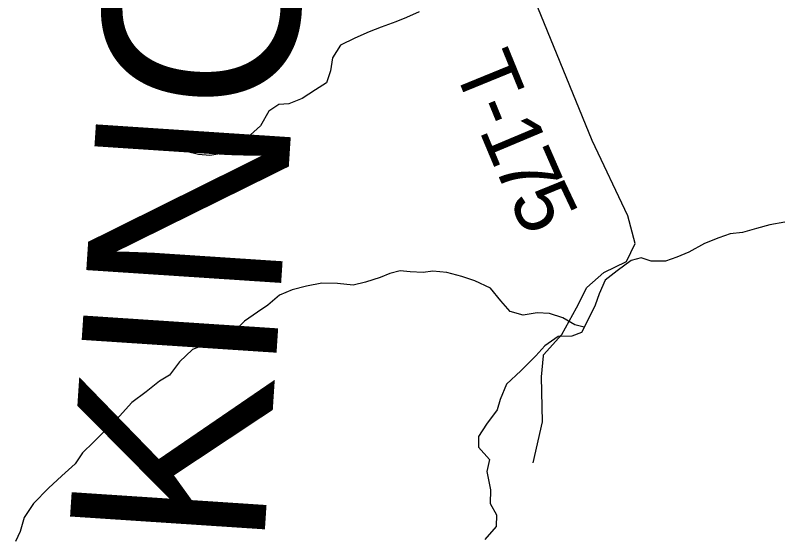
# Model space of a CAD drawing. Extents: x 0 to 42.5, y 0 to 22.
# Drawn here: x 8.1944 to 8.5674, y 14.792 to 15.0445 of the extents above; entities that cross this region are included whole.
import ezdxf

# ---------------------------------------------------------------- set-up
doc = ezdxf.new("R2010")
doc.units = 0
for name, color, linetype in [('GM_X_County_Text', 7, 'Continuous'), ('GM_X_Minor_River', 7, 'Continuous'), ('GM_X_Township_Road', 7, 'Continuous'), ('GM_X_Township_Road_Text', 7, 'Continuous')]:
    doc.layers.add(name, color=color, linetype=linetype)

msp = doc.modelspace()

# ---------------------------------------------------------------- linework, layer by layer
at = {"layer": 'GM_X_Minor_River'}
for p, q in [((8.38404, 15.04345), (8.37891, 15.0414)), ((8.39012, 15.04625), (8.38404, 15.04345)), ((8.37891, 15.0414), (8.37169, 15.03879)), ((8.366, 15.03655), (8.35897, 15.03356)), ((8.37169, 15.03879), (8.366, 15.03655)), ((8.35897, 15.03356), (8.35194, 15.03019)), ((8.35194, 15.03019), (8.34811, 15.02396)), ((8.34811, 15.02396), (8.34712, 15.01771)), ((8.34712, 15.01771), (8.34518, 15.01184)), ((8.34518, 15.01184), (8.33986, 15.00846)), ((8.33986, 15.00846), (8.33339, 15.00433)), ((8.33339, 15.00433), (8.32693, 15.00172)), ((8.32219, 15.00137), (8.31725, 14.99818)), ((8.32693, 15.00172), (8.32219, 15.00137)), ((8.31725, 14.99818), (8.31322, 14.991)), ((8.31322, 14.991), (8.30674, 14.98516)), ((8.30674, 14.98516), (8.3016, 14.98178)), ((8.25427, 14.98171), (8.24745, 14.98251)), ((8.26013, 14.98072), (8.25427, 14.98171)), ((8.26505, 14.98012), (8.26013, 14.98072)), ((8.27242, 14.97894), (8.26505, 14.98012)), ((8.3016, 14.98178), (8.29343, 14.97747)), ((8.27791, 14.97852), (8.27242, 14.97894)), ((8.2832, 14.97716), (8.27791, 14.97852)), ((8.28869, 14.97675), (8.2832, 14.97716)), ((8.29343, 14.97747), (8.28869, 14.97675)), ((8.38088, 14.92077), (8.37594, 14.91948)), ((8.3858, 14.92036), (8.38088, 14.92077)), ((8.39204, 14.91994), (8.3858, 14.92036)), ((8.39678, 14.92067), (8.39204, 14.91994)), ((8.40359, 14.92006), (8.39678, 14.92067)), ((8.3712, 14.91761), (8.36418, 14.91538)), ((8.37594, 14.91948), (8.3712, 14.91761)), ((8.41078, 14.91811), (8.40359, 14.92006)), ((8.4172, 14.91599), (8.41078, 14.91811)), ((8.33557, 14.91329), (8.32855, 14.91163)), ((8.34296, 14.91476), (8.33557, 14.91329)), ((8.35054, 14.91471), (8.34296, 14.91476)), ((8.35811, 14.9139), (8.35054, 14.91471)), ((8.36418, 14.91538), (8.35811, 14.9139)), ((8.42475, 14.91233), (8.4172, 14.91599)), ((8.32855, 14.91163), (8.32247, 14.90901)), ((8.42981, 14.90623), (8.42475, 14.91233)), ((8.32247, 14.90901), (8.31676, 14.90412)), ((8.43432, 14.90108), (8.42981, 14.90623)), ((8.31676, 14.90412), (8.31181, 14.90074)), ((8.31181, 14.90074), (8.30553, 14.89642)), ((8.44056, 14.89934), (8.43432, 14.90108)), ((8.44738, 14.90043), (8.44056, 14.89934)), ((8.45344, 14.9002), (8.44738, 14.90043)), ((8.45986, 14.89807), (8.45344, 14.9002)), ((8.46571, 14.89462), (8.45986, 14.89807)), ((8.30553, 14.89642), (8.3, 14.89115)), ((8.47019, 14.89347), (8.46571, 14.89462)), ((8.3, 14.89115), (8.29315, 14.88626)), ((8.28689, 14.88535), (8.28025, 14.88274)), ((8.29315, 14.88626), (8.28689, 14.88535)), ((8.28025, 14.88274), (8.27396, 14.87671)), ((8.27396, 14.87671), (8.26918, 14.87029)), ((8.26918, 14.87029), (8.26423, 14.86729)), ((8.26423, 14.86729), (8.25776, 14.86221)), ((8.25776, 14.86221), (8.2509, 14.85695)), ((8.2509, 14.85695), (8.2448, 14.85035)), ((8.2448, 14.85035), (8.23755, 14.84319)), ((8.23755, 14.84319), (8.23221, 14.83773)), ((8.23221, 14.83773), (8.22687, 14.83264)), ((8.22687, 14.83264), (8.22342, 14.82735)), ((8.22342, 14.82735), (8.21694, 14.82152)), ((8.21694, 14.82152), (8.21046, 14.81549)), ((8.21046, 14.81549), (8.20321, 14.80814)), ((8.20321, 14.80814), (8.19862, 14.80135)), ((8.19862, 14.80135), (8.19668, 14.79453)), ((8.19668, 14.79453), (8.19437, 14.78962))]:
    msp.add_line(p, q, dxfattribs=at)
msp.add_lwpolyline([(8.56756, 14.94441), (8.56016, 14.94313), (8.55371, 14.94127), (8.54688, 14.93942), (8.54101, 14.9387), (8.5355, 14.93684), (8.52848, 14.93404), (8.52087, 14.92992), (8.51517, 14.92749), (8.50967, 14.92544), (8.50266, 14.92548), (8.49775, 14.92703), (8.49301, 14.92574), (8.48616, 14.92085), (8.48044, 14.91634), (8.47737, 14.90972), (8.47543, 14.90423), (8.47235, 14.89762), (8.4689, 14.891), (8.46415, 14.88913), (8.45752, 14.88899), (8.45105, 14.88448), (8.44666, 14.87958), (8.43942, 14.87242), (8.43255, 14.86582), (8.42947, 14.85845), (8.42792, 14.85353), (8.42275, 14.84654), (8.41892, 14.8405), (8.41889, 14.83538), (8.42434, 14.82947), (8.42297, 14.8236), (8.4248, 14.81467), (8.42456, 14.80804), (8.42774, 14.80252), (8.42751, 14.79702), (8.42197, 14.79061)], dxfattribs=at)
at = {"layer": 'GM_X_Township_Road'}
for points in [[(8.45045, 14.87958), (8.4505, 14.88009), (8.45935, 14.89003), (8.46648, 14.9028), (8.47154, 14.91271), (8.47965, 14.91999), (8.49063, 14.92539), (8.49493, 14.93397), (8.49142, 14.94742), (8.47406, 14.98394), (8.44776, 15.0483), (8.44639, 15.05172), (8.43422, 15.08199), (8.41768, 15.08415), (8.40667, 15.08426), (8.40384, 15.08525)], [(8.44537, 14.82783), (8.44997, 14.84761), (8.44944, 14.86945), (8.45045, 14.87958)]]:
    msp.add_lwpolyline(points, dxfattribs=at)

# ---------------------------------------------------------------- texts
at = {"layer": 'GM_X_County_Text'}
msp.add_text('HOCKING COUNTY', height=0.094697, rotation=86.2285, dxfattribs=at).set_placement((8.29618, 14.5044))
at = {"layer": 'GM_X_Township_Road_Text'}
for s, rotation, p in [('T', 292.193, (8.4065, 15.01969)), ('-', 292.3234, (8.41455, 14.99995)), ('1', 292.7702, (8.41907, 14.98893)), ('7', 293.6721, (8.42604, 14.97235)), ('5', 295.3903, (8.43345, 14.95547))]:
    msp.add_text(s, height=0.02841, rotation=rotation, dxfattribs=at).set_placement(p)

doc.saveas('drawing.dxf')
